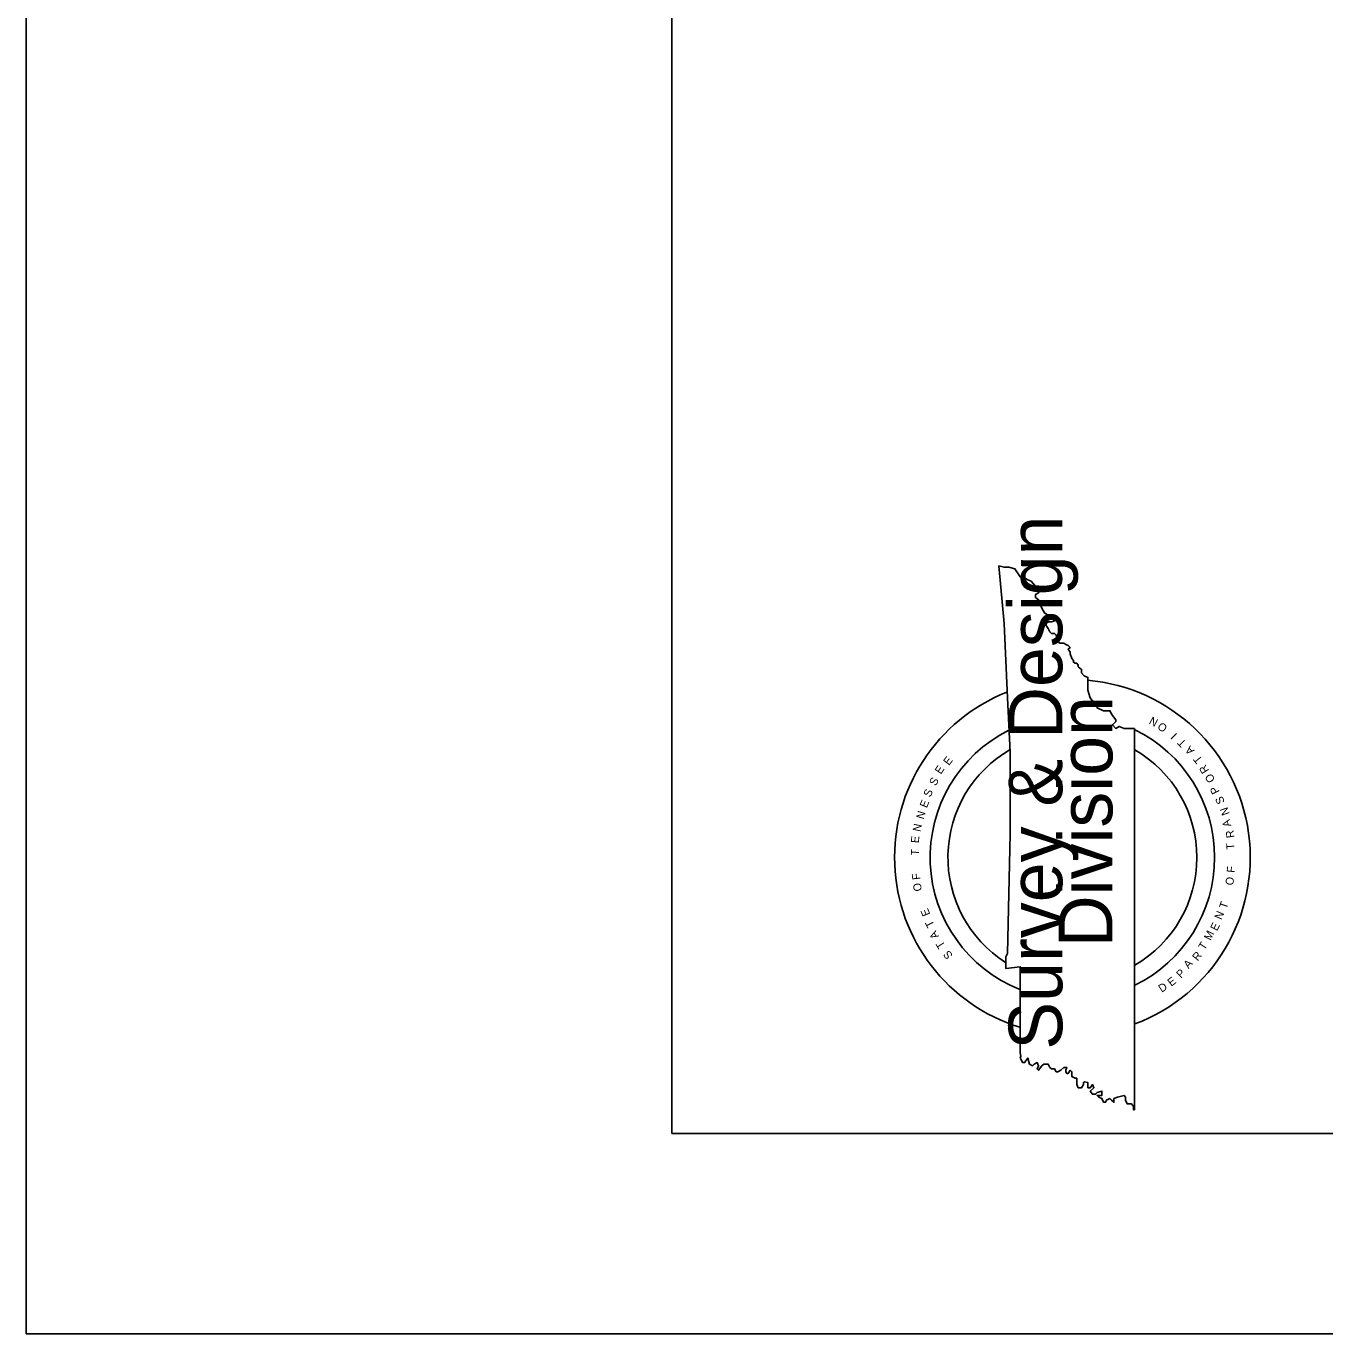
# Model space of a CAD drawing. Extents: x 1623795.1 to 1623879, y 427353.8 to 427391.8.
# Drawn here: x 1623834.903 to 1623838.143, y 427367.858 to 427371.121 of the extents above; entities that cross this region are included whole.
import ezdxf

# ---------------------------------------------------------------- set-up
doc = ezdxf.new("R2010")
doc.units = 0
for name, color, linetype in [('DESIGN - SCRATCH - User 1', 7, 'Continuous'), ('DESIGN - SHEET - Linework', 7, 'Continuous'), ('DESIGN - SHEET - Plot Shape', 7, 'Continuous')]:
    doc.layers.add(name, color=color, linetype=linetype)

msp = doc.modelspace()

# ---------------------------------------------------------------- linework, layer by layer
at = {"layer": 'DESIGN - SCRATCH - User 1'}
msp.add_lwpolyline([(1623836.514, 427389.358), (1623870.215, 427389.358), (1623870.215, 427368.358), (1623836.514, 427368.358)], close=True, dxfattribs=at)
at = {"layer": 'DESIGN - SHEET - Linework'}
for points in [[(1623837.33, 427369.775), (1623837.343, 427369.771), (1623837.355, 427369.771), (1623837.37, 427369.767), (1623837.37, 427369.767), (1623837.383, 427369.747), (1623837.394, 427369.745), (1623837.394, 427369.745), (1623837.394, 427369.745), (1623837.402, 427369.74), (1623837.41, 427369.736), (1623837.421, 427369.724), (1623837.429, 427369.724), (1623837.429, 427369.724), (1623837.433, 427369.716), (1623837.433, 427369.716), (1623837.429, 427369.707), (1623837.421, 427369.703), (1623837.421, 427369.703), (1623837.421, 427369.696), (1623837.421, 427369.696), (1623837.429, 427369.69), (1623837.429, 427369.69), (1623837.429, 427369.69), (1623837.429, 427369.69), (1623837.437, 427369.669), (1623837.444, 427369.657), (1623837.457, 427369.648), (1623837.469, 427369.642), (1623837.469, 427369.637), (1623837.469, 427369.637), (1623837.469, 427369.637), (1623837.461, 427369.635), (1623837.453, 427369.635), (1623837.448, 427369.631), (1623837.448, 427369.631), (1623837.448, 427369.631), (1623837.448, 427369.626), (1623837.453, 427369.618), (1623837.453, 427369.618), (1623837.457, 427369.61), (1623837.461, 427369.606), (1623837.469, 427369.606), (1623837.469, 427369.606), (1623837.473, 427369.602), (1623837.473, 427369.602), (1623837.477, 427369.589), (1623837.477, 427369.589), (1623837.481, 427369.582)], [(1623837.383, 427368.559), (1623837.383, 427368.774), (1623837.347, 427368.77), (1623837.347, 427368.799), (1623837.351, 427368.807), (1623837.358, 427369.106), (1623837.358, 427369.31), (1623837.351, 427369.445), (1623837.343, 427369.631), (1623837.33, 427369.775)], [(1623837.481, 427369.582), (1623837.481, 427369.582), (1623837.492, 427369.582), (1623837.497, 427369.578), (1623837.497, 427369.578), (1623837.503, 427369.576), (1623837.508, 427369.571), (1623837.503, 427369.567), (1623837.503, 427369.567), (1623837.508, 427369.559), (1623837.508, 427369.555), (1623837.512, 427369.543), (1623837.516, 427369.538), (1623837.516, 427369.538), (1623837.516, 427369.534), (1623837.52, 427369.532), (1623837.524, 427369.532), (1623837.528, 427369.527), (1623837.528, 427369.523), (1623837.536, 427369.516), (1623837.536, 427369.508), (1623837.543, 427369.5), (1623837.543, 427369.5), (1623837.543, 427369.5), (1623837.552, 427369.496), (1623837.552, 427369.464), (1623837.554, 427369.456), (1623837.554, 427369.456), (1623837.558, 427369.445), (1623837.558, 427369.445), (1623837.567, 427369.433), (1623837.567, 427369.433), (1623837.571, 427369.429), (1623837.575, 427369.424), (1623837.575, 427369.42), (1623837.591, 427369.413), (1623837.591, 427369.413), (1623837.607, 427369.413), (1623837.611, 427369.405), (1623837.613, 427369.401), (1623837.613, 427369.401), (1623837.622, 427369.39), (1623837.622, 427369.39), (1623837.622, 427369.386), (1623837.613, 427369.378), (1623837.613, 427369.378), (1623837.613, 427369.378), (1623837.622, 427369.369), (1623837.622, 427369.369), (1623837.63, 427369.374), (1623837.642, 427369.369), (1623837.65, 427369.369), (1623837.661, 427369.369), (1623837.668, 427369.369)], [(1623837.668, 427369.369), (1623837.668, 427368.417)], [(1623837.563, 427368.456), (1623837.558, 427368.464), (1623837.558, 427368.464), (1623837.567, 427368.472), (1623837.567, 427368.472), (1623837.563, 427368.48), (1623837.558, 427368.472), (1623837.552, 427368.472), (1623837.552, 427368.485), (1623837.552, 427368.485), (1623837.543, 427368.487), (1623837.541, 427368.485), (1623837.541, 427368.485), (1623837.541, 427368.48), (1623837.536, 427368.472), (1623837.528, 427368.472), (1623837.528, 427368.472), (1623837.528, 427368.472), (1623837.524, 427368.48), (1623837.524, 427368.496), (1623837.524, 427368.496), (1623837.52, 427368.496), (1623837.512, 427368.5), (1623837.512, 427368.512), (1623837.512, 427368.512), (1623837.508, 427368.516), (1623837.503, 427368.508), (1623837.499, 427368.508), (1623837.497, 427368.512), (1623837.497, 427368.516), (1623837.499, 427368.523), (1623837.492, 427368.523), (1623837.492, 427368.523), (1623837.484, 427368.516), (1623837.477, 427368.512), (1623837.477, 427368.512), (1623837.473, 427368.512), (1623837.469, 427368.519), (1623837.461, 427368.519), (1623837.457, 427368.523), (1623837.453, 427368.531), (1623837.442, 427368.531), (1623837.437, 427368.527), (1623837.429, 427368.516), (1623837.429, 427368.516), (1623837.425, 427368.519), (1623837.425, 427368.519), (1623837.429, 427368.527), (1623837.429, 427368.527), (1623837.425, 427368.535), (1623837.425, 427368.535), (1623837.418, 427368.531), (1623837.414, 427368.527), (1623837.406, 427368.531), (1623837.406, 427368.531), (1623837.402, 427368.546), (1623837.394, 427368.535), (1623837.389, 427368.535), (1623837.385, 427368.544), (1623837.383, 427368.546), (1623837.383, 427368.546), (1623837.385, 427368.551), (1623837.383, 427368.559), (1623837.383, 427368.559)], [(1623837.668, 427368.417), (1623837.666, 427368.417), (1623837.666, 427368.417), (1623837.666, 427368.421), (1623837.666, 427368.425), (1623837.661, 427368.432), (1623837.65, 427368.432), (1623837.646, 427368.441), (1623837.646, 427368.445), (1623837.646, 427368.449), (1623837.642, 427368.453), (1623837.626, 427368.449), (1623837.617, 427368.445), (1623837.617, 427368.436), (1623837.617, 427368.436), (1623837.617, 427368.436), (1623837.611, 427368.441), (1623837.607, 427368.445), (1623837.598, 427368.441), (1623837.598, 427368.441), (1623837.596, 427368.436), (1623837.591, 427368.436), (1623837.587, 427368.445), (1623837.587, 427368.445), (1623837.579, 427368.449), (1623837.579, 427368.449), (1623837.575, 427368.453), (1623837.575, 427368.453), (1623837.587, 427368.453), (1623837.587, 427368.464), (1623837.587, 427368.464), (1623837.575, 427368.46), (1623837.575, 427368.46), (1623837.575, 427368.46), (1623837.571, 427368.456), (1623837.571, 427368.456), (1623837.563, 427368.456), (1623837.563, 427368.456)]]:
    msp.add_lwpolyline(points, dxfattribs=at)
for radius, start, end in [(0.4437, 290.5761, 85.1103), (0.4437, 111.6407, 252.7624), (0.3549, 116.4861, 248.2585), (0.3549, 296.0602, 63.9398), (0.3106, 119.96, 237.4914), (0.3106, 300.1372, 59.8628)]:
    msp.add_arc((1623837.5133, 427369.0469), radius, start, end, dxfattribs=at)
at = {"layer": 'DESIGN - SHEET - Plot Shape'}
msp.add_lwpolyline([(1623834.903, 427389.858), (1623870.903, 427389.858), (1623870.903, 427367.858), (1623834.903, 427367.858)], close=True, dxfattribs=at)

# ---------------------------------------------------------------- texts
at = {"layer": 'DESIGN - SHEET - Linework'}
for s, height, rotation, p in [('Survey & Design', 0.13386, 90, (1623837.488, 427368.567)), ('Division', 0.13386, 90, (1623837.613, 427368.823)), ('N', 0.02, 151.6992, (1623837.729, 427369.39)), ('O', 0.02, 145.008, (1623837.752, 427369.374)), ('I', 0.02, 135, (1623837.776, 427369.354)), ('T', 0.02, 135, (1623837.799, 427369.334)), ('A', 0.02, 132.2737, (1623837.819, 427369.314)), ('E', 0.02, 52.125, (1623837.205, 427369.275)), ('T', 0.02, 128.6598, (1623837.839, 427369.291)), ('E', 0.02, 56.3099, (1623837.185, 427369.253)), ('R', 0.02, 122.4712, (1623837.855, 427369.264)), ('S', 0.02, 60.2551, (1623837.172, 427369.224)), ('O', 0.02, 118.6105, (1623837.87, 427369.24)), ('S', 0.02, 66.8014, (1623837.159, 427369.196)), ('P', 0.02, 116.565, (1623837.881, 427369.211)), ('S', 0.02, 113.1986, (1623837.894, 427369.185)), ('N', 0.02, 74.0546, (1623837.142, 427369.141)), ('E', 0.02, 68.1986, (1623837.15, 427369.169)), ('N', 0.02, 109.6538, (1623837.906, 427369.156)), ('N', 0.02, 78.6901, (1623837.134, 427369.11)), ('A', 0.02, 105.9454, (1623837.91, 427369.126)), ('E', 0.02, 84.8056, (1623837.13, 427369.082)), ('R', 0.02, 98.7462, (1623837.918, 427369.097)), ('T', 0.02, 85.6013, (1623837.13, 427369.051)), ('T', 0.02, 94.3987, (1623837.918, 427369.067)), ('F', 0.02, 95.7106, (1623837.134, 427368.992)), ('O', 0.02, 80.5377, (1623837.914, 427368.976)), ('F', 0.02, 84.2894, (1623837.918, 427369.008)), ('O', 0.02, 99.4623, (1623837.138, 427368.964)), ('T', 0.02, 71.5651, (1623837.898, 427368.917)), ('E', 0.02, 111.8014, (1623837.159, 427368.905)), ('N', 0.02, 66.8014, (1623837.885, 427368.89)), ('T', 0.02, 116.565, (1623837.17, 427368.878)), ('E', 0.02, 63.435, (1623837.874, 427368.862)), ('A', 0.02, 118.3008, (1623837.181, 427368.85)), ('T', 0.02, 122.4712, (1623837.197, 427368.827)), ('T', 0.02, 57.5288, (1623837.843, 427368.814)), ('M', 0.02, 63.435, (1623837.858, 427368.838)), ('S', 0.02, 129.8056, (1623837.216, 427368.803)), ('R', 0.02, 51.3402, (1623837.826, 427368.787)), ('A', 0.02, 47.7263, (1623837.803, 427368.768)), ('E', 0.02, 37.875, (1623837.76, 427368.724)), ('P', 0.02, 45, (1623837.784, 427368.744)), ('D', 0.02, 33.6901, (1623837.736, 427368.709))]:
    msp.add_text(s, height=height, rotation=rotation, dxfattribs=at).set_placement(p)

doc.saveas('drawing.dxf')
